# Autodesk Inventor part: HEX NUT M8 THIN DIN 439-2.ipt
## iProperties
IsCustomPart: 1
Created: 2006-02
Part Number: HEX NUT M8 THIN DIN 439-2.ipt
Material: Steel, Mild
Description: Hex Nut
Document SubType Name: Modeling
Standard: DIN 439
Designer: Andy Moles
Standards Organization: DIN
Language: en-US
Size Designation: M8
Categories: <MemberInstance><Categories><Category DisplayName="Fasteners" InternalName="e4da775c-781d-43d5-af7c-5136215cf5a6" Mnemonic="FSTN"><Category DisplayName="Nuts" I
Density: 7.86 g/cm^3
Mass: 3.25255 g
Surface Area: 4.33744 cm^2
Volume: 0.41381 cm^3
Author: Andy Moles
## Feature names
1. Body [Extrusion]
2. Chamfer1 [Revolution]
3. Thread [Hole]
4. Chamfer2
5. Chamfer3
